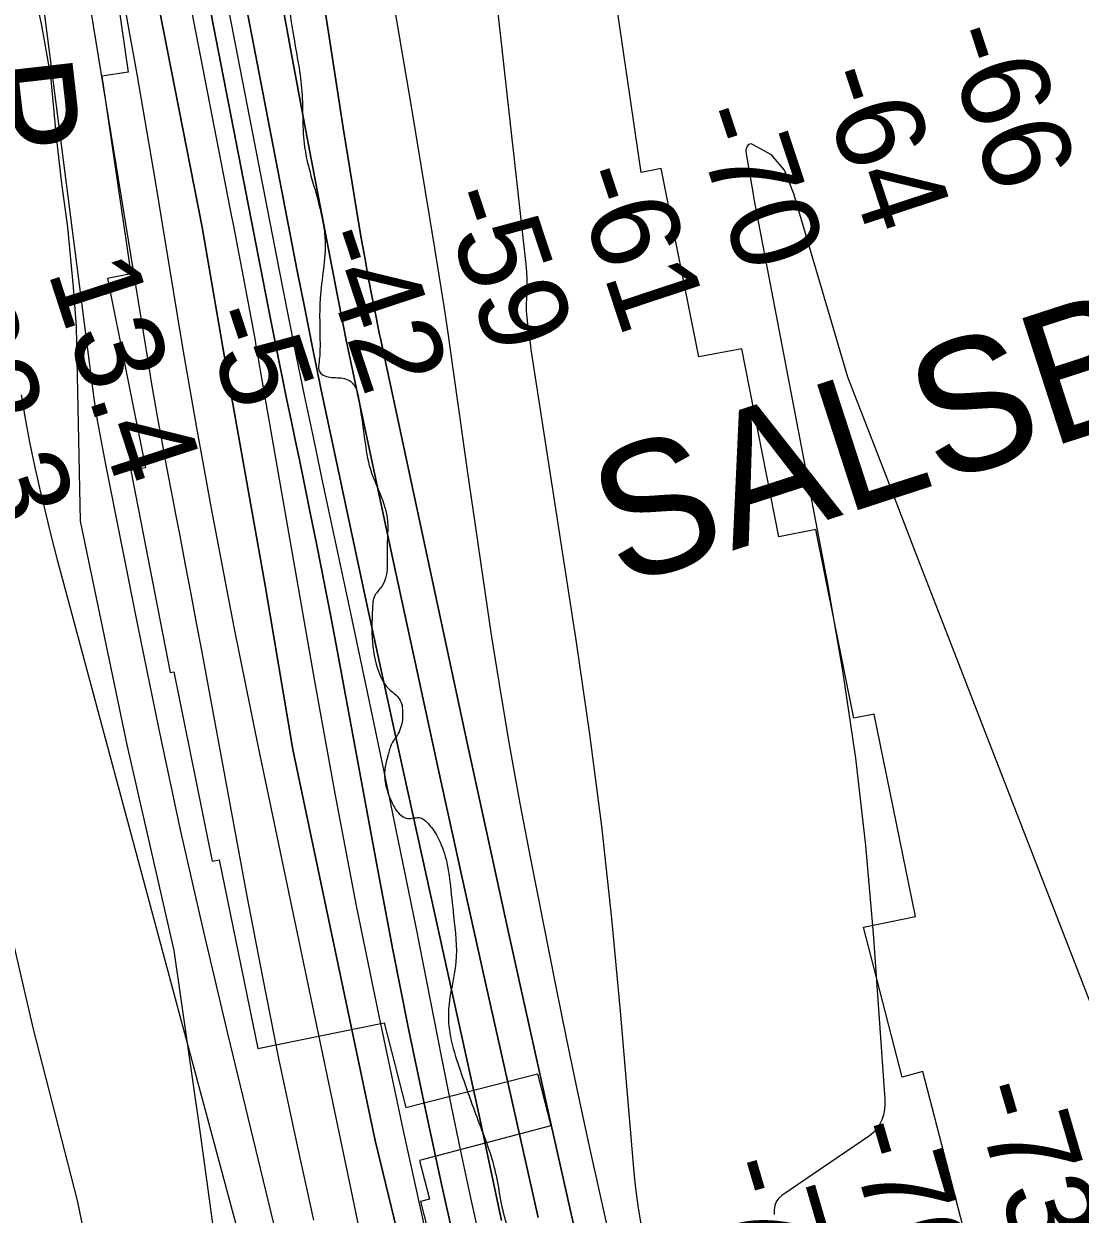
# Model space of a CAD drawing. Extents: x 3405885 to 3443815, y 558517 to 583997.
# Drawn here: x 3413052 to 3413853, y 579366 to 580269 of the extents above; entities that cross this region are included whole.
import ezdxf

# ---------------------------------------------------------------- set-up
doc = ezdxf.new("R2010")
doc.units = 0
for name, color, linetype in [('V-CHAN-NAID', 7, 'Continuous'), ('V-RIVR-EDGE', 7, 'Continuous'), ('V-RIVR-RANG', 7, 'Continuous'), ('V-RRAP-RVMT', 7, 'Continuous'), ('V-SITE-VEGE', 7, 'Continuous'), ('V-TOPO-DPTH', 7, 'Continuous'), ('V-TOPO-GNAM-IDEN', 7, 'Continuous'), ('V-TOPO-MAJR', 7, 'Continuous'), ('V-TOPO-MINR', 7, 'Continuous'), ('V-TOPO-WATR', 7, 'Continuous'), ('V-TOPO-WATR-IDEN', 7, 'Continuous')]:
    doc.layers.add(name, color=color, linetype=linetype)

msp = doc.modelspace()

# ---------------------------------------------------------------- linework, layer by layer
at = {"layer": 'V-RIVR-EDGE'}
msp.add_spline([(3412820.89, 582098.27), (3412817.84, 582058.01), (3412815.57, 582029.5), (3412817.71, 582007.93), (3412825.69, 581980.13), (3412850.3, 581879.91), (3412863.71, 581832.72), (3412872.03, 581799.07), (3412892.31, 581722.25), (3412903.17, 581678.36), (3412909.64, 581634.84), (3412920.52, 581598.99), (3412933.97, 581569.35), (3412943.42, 581548.49), (3412954.66, 581511.18), (3412955.33, 581484.86), (3412959.66, 581464.01), (3412965.14, 581459.61), (3412977.89, 581444.95), (3412992.43, 581409.09), (3413006.55, 581353.13), (3413015.19, 581302.3), (3413018.74, 581260.25), (3413013.93, 581236.14), (3413008.78, 581220.07), (3413005.09, 581206.55), (3413003.59, 581194.49), (3413004.66, 581180.23), (3413009.33, 581149.15), (3413020.58, 581117.32), (3413042.04, 581073.03), (3413073.01, 581031.28), (3413081.02, 581018.1), (3413088.65, 580999.81), (3413094.45, 580977.86), (3413100.2, 580939.1), (3413102.69, 580912.04), (3413106.3, 580894.12), (3413113.53, 580861.93), (3413124.77, 580824.25), (3413140.02, 580781.45), (3413146.54, 580756.94), (3413148.69, 580740.12), (3413153.76, 580721.83), (3413161, 580692.57), (3413184.21, 580615.75), (3413193.99, 580582.46), (3413204.19, 580568.17), (3413207.83, 580561.59), (3413213.98, 580535.25), (3413232.08, 580461.73), (3413243.98, 580397.73), (3413252.99, 580345.07), (3413251.86, 580330.82), (3413256.43, 580258.43), (3413262.55, 580217.47), (3413264.64, 580175.43), (3413271.51, 580146.53), (3413278.75, 580117.27), (3413280.18, 580104.84), (3413276.41, 580060.61), (3413276.33, 580025.89), (3413275.56, 580012.36), (3413275.55, 580006.15), (3413277.73, 580003.22), (3413287.96, 580000.64), (3413298.56, 579998.42), (3413303.66, 579992.19), (3413305.47, 579985.24), (3413310.15, 579953.79), (3413314.48, 579931.12), (3413321.02, 579914.65), (3413327.18, 579894.53), (3413327.12, 579868.94), (3413323.4, 579842.63), (3413317.9, 579835.33), (3413316.04, 579824.74), (3413315.63, 579806.46), (3413319.95, 579780.13), (3413327.96, 579765.12), (3413335.62, 579758.16), (3413338.16, 579753.4), (3413338.88, 579747.55), (3413338.87, 579742.8), (3413335.55, 579730.74), (3413330.78, 579723.08), (3413327.83, 579714.31), (3413325.24, 579701.16), (3413326.67, 579689.46), (3413332.12, 579675.92), (3413338.32, 579668.23), (3413342.7, 579666.39), (3413352.57, 579666.73), (3413357.32, 579663.43), (3413365.33, 579652.44), (3413371.87, 579635.24), (3413374.75, 579618.42), (3413377.61, 579592.46), (3413379.35, 579557.36), (3413373.78, 579521.55), (3413375.19, 579501.08), (3413382.08, 579476.94), (3413395.15, 579439.98), (3413408.57, 579400.84), (3413417.61, 579358.78), (3413445.24, 579297.66), (3413449.93, 579271.7), (3413449.83, 579233.31), (3413439.49, 579191.3), (3413438.74, 579182.16), (3413439.81, 579172.66), (3413446, 579161.68), (3413464.94, 579134.58), (3413487.52, 579101.62), (3413496.96, 579074.91), (3413502.74, 579046.39), (3413506.69, 579018.23), (3413510.64, 578990.8), (3413518.59, 578952.4), (3413529.8, 578903.76), (3413538.13, 578871.57), (3413547.91, 578834.62), (3413558.39, 578787.44), (3413566.69, 578743.19), (3413574.63, 578699.3), (3413585.07, 578637.13), (3413595.16, 578577.16), (3413599.47, 578547.54), (3413610.73, 578516.07), (3413620.2, 578503.99), (3413626.04, 578499.22), (3413635.54, 578497.01), (3413635.9, 578494.45), (3413634.06, 578490.06), (3413632.22, 578487.14), (3413632.2, 578479.47), (3413633.24, 578454.97), (3413642.22, 578390.98), (3413644.34, 578359.17), (3413649.04, 578338.69), (3413656.31, 578322.22), (3413667.62, 578313.79), (3413676.01, 578309.01), (3413684.41, 578305.34), (3413688.79, 578300.21), (3413697.9, 578288.49), (3413702.24, 578272.39), (3413709.14, 578250.81), (3413714.94, 578233.25), (3413728.72, 578187.15), (3413734.84, 578151.32), (3413738.77, 578114.39), (3413740.53, 578084.04), (3413746.68, 578059.17), (3413750.66, 578043.44), (3413751.33, 578020.04), (3413747.61, 577990.81), (3413742.03, 577955), (3413736.87, 577934.54), (3413735.37, 577919.56), (3413733.5, 577904.21), (3413737.1, 577880.07), (3413741.45, 577864.71), (3413741.44, 577863.25), (3413750.22, 577865.78), (3413754.97, 577862.85), (3413760.04, 577845.65), (3413773.82, 577798.1), (3413781.78, 577765.18), (3413793.01, 577724.94), (3413796.97, 577700.44), (3413803.39, 577637.18), (3413804.43, 577613.79), (3413807.67, 577591.85), (3413815.27, 577561.12), (3413829.43, 577524.9), (3413841.79, 577493.79), (3413853.78, 577465.98), (3413863.23, 577445.49), (3413869.78, 577431.22), (3413869.77, 577426.1), (3413869.73, 577412.94), (3413868.94, 577389.55), (3413869.22, 577352.99), (3413871.01, 577339.83), (3413873.91, 577328.49), (3413883, 577306.53), (3413889.53, 577287.87), (3413905.14, 577244.33), (3413913.47, 577211.05), (3413925.41, 577161.3), (3413947.56, 577101.66), (3413958.82, 577073.49), (3413969.01, 577057.38), (3413973, 577043.85), (3413979.88, 577014.58), (3414001.97, 576930.82), (3414004.47, 576907.42), (3414006.27, 576897.18), (3414015, 576880.34), (3414024.45, 576858.75), (3414031.34, 576835.7), (3414040.76, 576799.49), (3414054.16, 576750.11), (3414062.48, 576713.9), (3414069.34, 576679.89), (3414074.43, 576668.54), (3414075.15, 576663.42), (3414103.1, 576586.22), (3414107.44, 576564.64), (3414115.39, 576529.17), (3414118.99, 576507.96), (3414142.2, 576433.69), (3414153.45, 576399.3), (3414159.61, 576378.45), (3414164.66, 576348.83), (3414174.05, 576303.84), (3414178, 576274.95), (3414184.15, 576248.25), (3414191.06, 576233.98), (3414204.14, 576202.15), (3414212.13, 576179.46), (3414242.98, 576089.46), (3414264.75, 576025.44), (3414269.45, 576005.68), (3414269.43, 575994.35), (3414267.65, 575989.11)], degree=3, dxfattribs=at)
at = {"layer": 'V-RRAP-RVMT'}
for points in [[(3413113.33, 580352.85), (3413130.92, 580232.14), (3413110.93, 580229.29), (3413132.89, 580079.38), (3413115.11, 580075.83), (3413143.91, 579932.21), (3413132.92, 579930.07), (3413162.8, 579777.07), (3413165.62, 579777.63), (3413194.63, 579633.94), (3413199.98, 579635.04), (3413229.13, 579491.81), (3413324.99, 579511.36), (3413341.38, 579447.28), (3413441.13, 579472.79), (3413451.25, 579433.23), (3413351.79, 579406.98), (3413359.26, 579377.65), (3413352.61, 579375.95), (3413391.36, 579223.79), (3413542.64, 579262.32), (3413575.63, 579132.61)], [(3413802.96, 579179.75), (3413767.01, 579320.88), (3413772.64, 579322.34), (3413733.29, 579474.36), (3413717.55, 579470.29), (3413688.27, 579584), (3413727.66, 579591.95), (3413696.44, 579745.39), (3413681.08, 579742.3), (3413652.2, 579885.5), (3413624.02, 579879.97), (3413596.19, 580022.49), (3413563.45, 580016.32), (3413534.82, 580159.2), (3413519.81, 580156.18), (3413500.87, 580285.56)]]:
    msp.add_lwpolyline(points, dxfattribs=at)
at = {"layer": 'V-SITE-VEGE'}
for points in [[(3413058.31, 580300.08), (3413065.17, 580267.6), (3413071.99, 580229.22), (3413076.41, 580183.19), (3413080.31, 580147.77), (3413084.8, 580114.72), (3413089.22, 580069.27), (3413091.39, 580039.18), (3413094.54, 579891.71), (3413129.99, 579722.2), (3413165.53, 579566.26), (3413185.27, 579429.3), (3413198.77, 579329.54)], [(3413128.01, 579204.15), (3413092.58, 579376.6), (3413059.23, 579506.58), (3413016.9, 579688.16)]]:
    msp.add_lwpolyline(points, dxfattribs=at)
at = {"layer": 'V-TOPO-DPTH'}
for points in [[(3413113.8, 580487.79), (3413186.95, 580114.69), (3413203.74, 580017.58), (3413234.81, 579842.97), (3413255.79, 579718.61), (3413318.06, 579422.16), (3413354.3, 579273.08), (3413358.52, 579257.74), (3413360.2, 579247.52), (3413367.73, 579194.71), (3413376.93, 579127.43), (3413384.52, 579097.61), (3413411.48, 578982.6), (3413448.52, 578813.93), (3413532.73, 578434.84), (3413535.26, 578425.47), (3413536.94, 578418.66), (3413621.15, 578042.12), (3413698.65, 577706.48), (3413704.56, 577683.47), (3413708.77, 577666.43), (3413718.9, 577631.5), (3413770.38, 577445.77)], [(3413770.38, 577445.77), (3413718.9, 577631.5), (3413708.77, 577666.43), (3413704.56, 577683.47), (3413698.65, 577706.48), (3413621.15, 578042.12), (3413536.94, 578418.66), (3413535.26, 578425.47), (3413532.73, 578434.84), (3413448.52, 578813.93), (3413411.48, 578982.6), (3413384.52, 579097.61), (3413376.93, 579127.43), (3413367.73, 579194.71), (3413360.2, 579247.52), (3413358.52, 579257.74), (3413354.3, 579273.08), (3413318.06, 579422.16), (3413255.79, 579718.61), (3413234.81, 579842.97), (3413203.74, 580017.58), (3413186.95, 580114.69), (3413113.8, 580487.79)], [(3413154.11, 580480.31), (3413239.04, 580043.84), (3413242.01, 580028.74), (3413245.03, 580013.65), (3413248.12, 579998.58), (3413251.25, 579983.51), (3413254.41, 579968.45), (3413257.55, 579953.39), (3413260.68, 579938.32), (3413263.8, 579923.25), (3413268.72, 579899.38), (3413274.2, 579872.36), (3413279.57, 579845.31), (3413284.76, 579818.23), (3413289.84, 579791.13), (3413320.07, 579627.01), (3413331.51, 579566.81), (3413343.4, 579506.69), (3413355.97, 579446.72), (3413368.99, 579386.84), (3413385.63, 579312.32)], [(3413385.63, 579312.32), (3413368.99, 579386.84), (3413355.97, 579446.72), (3413343.4, 579506.69), (3413331.51, 579566.81), (3413320.07, 579627.01), (3413289.84, 579791.13), (3413284.76, 579818.23), (3413279.57, 579845.31), (3413274.2, 579872.36), (3413268.72, 579899.38), (3413263.8, 579923.25), (3413260.68, 579938.32), (3413257.55, 579953.39), (3413254.41, 579968.45), (3413251.25, 579983.51), (3413248.12, 579998.58), (3413245.03, 580013.65), (3413242.01, 580028.74), (3413239.04, 580043.84), (3413154.11, 580480.31)], [(3413413.93, 579361.6), (3413409.7, 579381.78), (3413405.42, 579401.96), (3413401.07, 579422.13), (3413396.68, 579442.28), (3413333.3, 579730.32), (3413322.67, 579778.9), (3413312.11, 579827.5), (3413301.67, 579876.13), (3413291.29, 579924.77), (3413283.23, 579962.76), (3413277.02, 579992.43), (3413270.92, 580022.13), (3413264.97, 580051.85), (3413259.13, 580081.6), (3413231.46, 580224.53), (3413213.71, 580316.57)], [(3413213.71, 580316.57), (3413231.46, 580224.53), (3413259.13, 580081.6), (3413264.97, 580051.85), (3413270.92, 580022.13), (3413277.02, 579992.43), (3413283.23, 579962.76), (3413291.29, 579924.77), (3413301.67, 579876.13), (3413312.11, 579827.5), (3413322.67, 579778.9), (3413333.3, 579730.32), (3413396.68, 579442.28), (3413401.07, 579422.13), (3413405.42, 579401.96), (3413409.7, 579381.78), (3413413.93, 579361.6)], [(3413098.92, 580301.97), (3413146.02, 580011.81), (3413148.43, 579997.28), (3413150.91, 579982.77), (3413153.48, 579968.27), (3413156.11, 579953.78), (3413158.81, 579939.3), (3413161.53, 579924.82), (3413164.28, 579910.35), (3413167.05, 579895.89), (3413169.97, 579880.72), (3413174.19, 579858.67), (3413178.38, 579836.62), (3413182.52, 579814.56), (3413186.63, 579792.48), (3413220.88, 579607.51), (3413232.66, 579545.87), (3413244.91, 579484.32), (3413257.87, 579422.92), (3413271.3, 579361.61)], [(3413441.81, 579363.7), (3413402.36, 579539.52), (3413384.16, 579621.23), (3413366.13, 579702.97), (3413348.37, 579784.77), (3413330.78, 579866.61), (3413302.97, 579996.98), (3413299.46, 580013.67), (3413296.01, 580030.37), (3413292.67, 580047.09), (3413289.38, 580063.83), (3413274.92, 580138.73), (3413264.59, 580192.95), (3413254.43, 580247.2), (3413244.54, 580301.5)], [(3413441.81, 579363.7), (3413402.36, 579539.52), (3413384.16, 579621.23), (3413366.13, 579702.97), (3413348.37, 579784.77), (3413330.78, 579866.61), (3413302.97, 579996.98), (3413299.46, 580013.67), (3413296.01, 580030.37), (3413292.67, 580047.09), (3413289.38, 580063.83), (3413274.92, 580138.73), (3413264.59, 580192.95), (3413254.43, 580247.2), (3413244.54, 580301.5)], [(3413278.77, 580288.63), (3413283.72, 580255.78), (3413288.77, 580222.94), (3413293.97, 580190.12), (3413299.25, 580157.32), (3413305.59, 580118.56), (3413307.84, 580105.16), (3413310.18, 580091.77), (3413312.64, 580078.41), (3413315.18, 580065.06), (3413318.8, 580046.52), (3413319.6, 580042.46), (3413320.42, 580038.39), (3413321.26, 580034.34), (3413322.12, 580030.28), (3413387.91, 579723.75), (3413403.46, 579651.82), (3413419.16, 579579.92), (3413435.07, 579508.06), (3413451.12, 579436.24), (3413471.39, 579346.19)], [(3413278.77, 580288.63), (3413283.72, 580255.78), (3413288.77, 580222.94), (3413293.97, 580190.12), (3413299.25, 580157.32), (3413305.59, 580118.56), (3413307.84, 580105.16), (3413310.18, 580091.77), (3413312.64, 580078.41), (3413315.18, 580065.06), (3413318.8, 580046.52), (3413319.6, 580042.46), (3413320.42, 580038.39), (3413321.26, 580034.34), (3413322.12, 580030.28), (3413387.91, 579723.75), (3413403.46, 579651.82), (3413419.16, 579579.92), (3413435.07, 579508.06), (3413451.12, 579436.24), (3413471.39, 579346.19)]]:
    msp.add_lwpolyline(points, dxfattribs=at)
at = {"layer": 'V-TOPO-MAJR'}
msp.add_lwpolyline([(3413500.41, 579329.02), (3413489.1, 579379.06), (3413480.27, 579418.88), (3413471.65, 579458.73), (3413463.35, 579498.66), (3413455.26, 579538.63), (3413436.05, 579635.62), (3413428.03, 579677.61), (3413420.39, 579719.68), (3413413.34, 579761.84), (3413406.67, 579804.07), (3413406.44, 579805.64), (3413400.24, 579847.14), (3413394.14, 579888.66), (3413388.17, 579930.2), (3413382.29, 579971.75), (3413376.84, 580010.69), (3413373.67, 580032.77), (3413370.38, 580054.83), (3413366.93, 580076.87), (3413363.36, 580098.89), (3413345.59, 580206.12), (3413332.72, 580281.69)], dxfattribs=at)
at = {"layer": 'V-TOPO-MINR'}
for points in [[(3413114.16, 580612.05), (3413208.03, 580129.1), (3413211.39, 580111.73), (3413214.72, 580094.35), (3413218.02, 580076.98), (3413221.3, 580059.59), (3413226.34, 580032.75), (3413227.07, 580028.78), (3413227.79, 580024.81), (3413228.47, 580020.83), (3413229.14, 580016.85), (3413229.98, 580011.78), (3413230.46, 580008.89), (3413230.71, 580007.45), (3413230.96, 580006), (3413272.14, 579770.33), (3413287.6, 579685.16), (3413303.79, 579600.14), (3413321.1, 579515.34), (3413339.14, 579430.69), (3413362.08, 579326.43)], [(3413037.54, 580507.54), (3413104.86, 579984.7), (3413107.44, 579968.45), (3413110.3, 579952.26), (3413113.36, 579936.09), (3413137.86, 579812.83), (3413153.8, 579735.17), (3413170.39, 579657.65), (3413187.95, 579580.34), (3413206.16, 579503.18), (3413266.19, 579255.77)], [(3413154.11, 580480.31), (3413239.04, 580043.84), (3413242.01, 580028.74), (3413245.03, 580013.65), (3413248.12, 579998.58), (3413251.25, 579983.51), (3413254.41, 579968.45), (3413257.55, 579953.39), (3413260.68, 579938.32), (3413263.8, 579923.25), (3413268.72, 579899.38), (3413274.2, 579872.36), (3413279.57, 579845.31), (3413284.76, 579818.23), (3413289.84, 579791.13), (3413320.07, 579627.01), (3413331.51, 579566.81), (3413343.4, 579506.69), (3413355.97, 579446.72), (3413368.99, 579386.84), (3413385.63, 579312.32)], [(3413401.47, 580360.87), (3413412.39, 580265.78), (3413432.36, 580086.27), (3413432.83, 580080.88), (3413433.12, 580075.49), (3413433.14, 580070.09), (3413432.99, 580064.69), (3413432.8, 580061.03), (3413432.67, 580056.12), (3413432.72, 580051.22), (3413433.03, 580046.32), (3413433.51, 580041.44), (3413434.15, 580036.56), (3413434.82, 580031.68), (3413435.52, 580026.82), (3413436.25, 580021.95), (3413470.6, 579799.98), (3413480.65, 579730.25), (3413489.72, 579660.4), (3413497.33, 579590.37), (3413503.97, 579520.23), (3413513.99, 579400.96), (3413515.03, 579390.39), (3413516.26, 579379.83), (3413517.78, 579369.32), (3413519.5, 579358.83)], [(3413193.17, 580351.21), (3413245.44, 580081.81), (3413251.72, 580049.86), (3413258.11, 580017.92), (3413264.65, 579986.02), (3413271.3, 579954.14), (3413278.04, 579922.28), (3413284.79, 579890.42), (3413291.55, 579858.56), (3413298.31, 579826.71), (3413313.85, 579753.64), (3413325.74, 579697.1), (3413337.43, 579640.53), (3413348.86, 579583.9), (3413360.1, 579527.23), (3413368.38, 579484.89), (3413375.5, 579449.4), (3413382.81, 579413.94), (3413390.44, 579378.56), (3413398.28, 579343.21)], [(3413123.12, 580310.26), (3413137.44, 580230.7), (3413151.05, 580151), (3413167.68, 580049.6), (3413172.54, 580020.53), (3413177.52, 579991.48), (3413182.67, 579962.45), (3413187.94, 579933.45), (3413193.88, 579901.35), (3413202.37, 579856.35), (3413211.06, 579811.39), (3413220.06, 579766.49), (3413229.27, 579721.62), (3413264.79, 579551.62), (3413272.62, 579514.19), (3413280.44, 579476.75), (3413288.25, 579439.32), (3413296.07, 579401.88), (3413303.42, 579366.67), (3413307.58, 579346.84)], [(3413213.71, 580316.57), (3413231.46, 580224.53), (3413259.13, 580081.6), (3413264.97, 580051.85), (3413270.92, 580022.13), (3413277.02, 579992.43), (3413283.23, 579962.76), (3413291.29, 579924.77), (3413301.67, 579876.13), (3413312.11, 579827.5), (3413322.67, 579778.9), (3413333.3, 579730.32), (3413396.68, 579442.28), (3413401.07, 579422.13), (3413405.42, 579401.96), (3413409.7, 579381.78), (3413413.93, 579361.6)], [(3413098.92, 580301.97), (3413146.02, 580011.81), (3413148.43, 579997.28), (3413150.91, 579982.77), (3413153.48, 579968.27), (3413156.11, 579953.78), (3413158.81, 579939.3), (3413161.53, 579924.82), (3413164.28, 579910.35), (3413167.05, 579895.89), (3413169.97, 579880.72), (3413174.19, 579858.67), (3413178.38, 579836.62), (3413182.52, 579814.56), (3413186.63, 579792.48), (3413220.88, 579607.51), (3413232.66, 579545.87), (3413244.91, 579484.32), (3413257.87, 579422.92), (3413271.3, 579361.61)], [(3413244.54, 580301.5), (3413254.43, 580247.2), (3413264.59, 580192.95), (3413274.92, 580138.73), (3413289.38, 580063.83), (3413292.67, 580047.09), (3413296.01, 580030.37), (3413299.46, 580013.67), (3413302.97, 579996.98), (3413330.78, 579866.61), (3413348.37, 579784.77), (3413366.13, 579702.97), (3413384.16, 579621.23), (3413402.36, 579539.52), (3413441.81, 579363.7)], [(3413471.39, 579346.19), (3413451.12, 579436.24), (3413435.07, 579508.06), (3413419.16, 579579.92), (3413403.46, 579651.82), (3413387.91, 579723.75), (3413322.12, 580030.28), (3413321.26, 580034.34), (3413320.42, 580038.39), (3413319.6, 580042.46), (3413318.8, 580046.52), (3413315.18, 580065.06), (3413312.64, 580078.41), (3413310.18, 580091.77), (3413307.84, 580105.16), (3413305.59, 580118.56), (3413299.25, 580157.32), (3413293.97, 580190.12), (3413288.77, 580222.94), (3413283.72, 580255.78), (3413278.77, 580288.63)], [(3413897.47, 579430.63), (3413782.34, 579727.51), (3413755.84, 579795.88), (3413729.35, 579864.26), (3413702.87, 579932.64), (3413676.41, 580001.03), (3413635.49, 580140.09), (3413628.4, 580157.93), (3413618.63, 580169.54), (3413604.07, 580177.36), (3413603.18, 580177.84), (3413602.17, 580177.74), (3413601.08, 580177.27), (3413600.13, 580176.1), (3413599.19, 580173.44), (3413599.2, 580171.93), (3413604.57, 580139.76), (3413605.23, 580135.89), (3413605.91, 580132.04), (3413606.62, 580128.18), (3413607.34, 580124.33), (3413661.01, 579844.21), (3413672.42, 579778.28), (3413682.26, 579712.15), (3413689.72, 579645.72), (3413695.61, 579579.07), (3413704.44, 579453.5), (3413704.46, 579449.52), (3413704.16, 579445.59), (3413703.38, 579441.72), (3413702.26, 579437.91), (3413700.58, 579434.36), (3413698.52, 579431.11), (3413695.88, 579428.31), (3413692.87, 579425.8), (3413626.38, 579380.37), (3413624.01, 579378.16), (3413622.17, 579375.65), (3413621.14, 579372.73), (3413620.65, 579369.51), (3413620.7, 579366.05)], [(3413049.76, 579987.68), (3413052.79, 579969.61), (3413056.1, 579951.6), (3413059.84, 579933.67), (3413063.86, 579915.79), (3413068.18, 579897.98), (3413072.6, 579880.19), (3413077.18, 579862.45), (3413081.86, 579844.73), (3413248.45, 579225.18)]]:
    msp.add_lwpolyline(points, dxfattribs=at)
at = {"layer": 'V-TOPO-WATR'}
msp.add_lwpolyline([(3413770.38, 577445.77), (3413718.9, 577631.5), (3413708.77, 577666.43), (3413704.56, 577683.47), (3413698.65, 577706.48), (3413621.15, 578042.12), (3413536.94, 578418.66), (3413535.26, 578425.47), (3413532.73, 578434.84), (3413448.52, 578813.93), (3413411.48, 578982.6), (3413384.52, 579097.61), (3413376.93, 579127.43), (3413367.73, 579194.71), (3413360.2, 579247.52), (3413358.52, 579257.74), (3413354.3, 579273.08), (3413318.06, 579422.16), (3413255.79, 579718.61), (3413234.81, 579842.97), (3413203.74, 580017.58), (3413186.95, 580114.69), (3413113.8, 580487.79)], dxfattribs=at)

# ---------------------------------------------------------------- texts
at = {"layer": 'V-CHAN-NAID'}
msp.add_text('IMC PHOSPHATES FAUSTINA ', height=100, rotation=16.17216, dxfattribs=at).set_placement((3413668.2, 579099.53))
at = {"layer": 'V-RIVR-RANG'}
for s, rotation, p in [('-66', 288.30189, (3413746.94, 580260.66)), ('-64', 288.30189, (3413652.01, 580229.24)), ('-70', 288.30189, (3413556.49, 580199.58)), ('-61', 288.30189, (3413466.28, 580153.89)), ('-59', 288.30189, (3413366.29, 580137.74)), ('-42', 288.30189, (3413271.02, 580107.33)), ('13.4', 288.01833, (3413069.64, 580081.15)), ('22.3', 288.01833, (3412974.62, 580049.98)), ('-5', 288.30189, (3413185.44, 580047.61)), ('-73', 286.31147, (3413769.09, 579460.8)), ('-70', 286.31147, (3413673.71, 579430.68)), ('-70', 286.31147, (3413577.66, 579402.83))]:
    msp.add_text(s, height=67, rotation=rotation, dxfattribs=at).set_placement(p)
at = {"layer": 'V-TOPO-GNAM-IDEN'}
msp.add_text('SALSBURG LDG.', height=99.9998, rotation=17.94985, dxfattribs=at).set_placement((3413503.89, 579841.78))
at = {"layer": 'V-TOPO-WATR-IDEN'}
msp.add_text('L.W.R.P.', height=83, rotation=276.53348, dxfattribs=at).set_placement((3412966.62, 580575.79))

doc.saveas('drawing.dxf')
